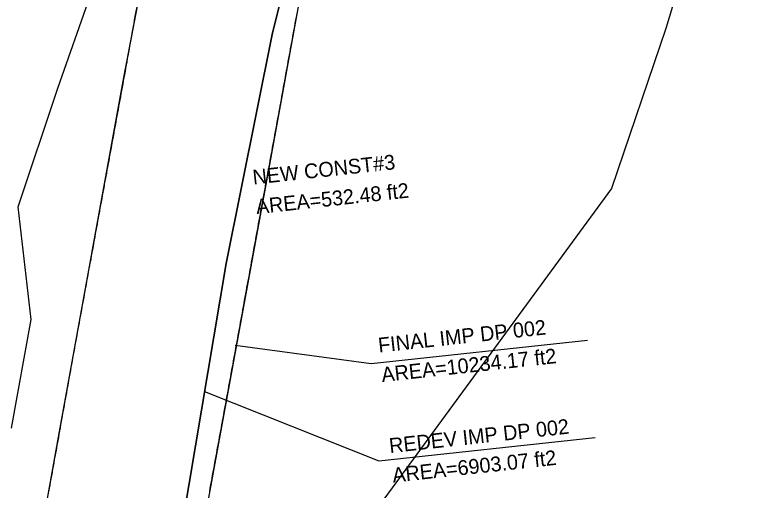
# Model space of a CAD drawing. Extents: x 1509538 to 1510847, y 401283 to 402022.
# Drawn here: x 1509743.9 to 1509883.9, y 401419.8 to 401509.5 of the extents above; entities that cross this region are included whole.
import ezdxf

# ---------------------------------------------------------------- set-up
doc = ezdxf.new("R2010")
doc.units = 0
for name, color, linetype in [('LAWE_P_T', 7, 'Continuous'), ('LDEFAULT_P', 7, 'Continuous'), ('Level 10', 7, 'Continuous'), ('Level 2', 7, 'Continuous'), ('Level 24', 7, 'Continuous'), ('Level 3', 7, 'Continuous'), ('Level 7', 7, 'Continuous')]:
    doc.layers.add(name, color=color, linetype=linetype)

msp = doc.modelspace()

# ---------------------------------------------------------------- linework, layer by layer
at = {"layer": 'LDEFAULT_P'}
for points in [[(1509785.49, 401447.11), (1509811.2, 401443.65), (1509852.03, 401448.1)], [(1509779.72, 401438.42), (1509812.63, 401425.29), (1509853.46, 401429.74)]]:
    msp.add_lwpolyline(points, dxfattribs=at)
at = {"layer": 'Level 10'}
for p, q in [((1509783.79, 401462.54), (1509792.46, 401505.8)), ((1509765.37, 401502.44), (1509765.29, 401502.03)), ((1509762.29, 401485.62), (1509762.23, 401485.31)), ((1509761.74, 401482.62), (1509761.69, 401482.35)), ((1509759.89, 401472.52), (1509759.76, 401471.8)), ((1509759.98, 401473.01), (1509759.89, 401472.52)), ((1509759.76, 401471.8), (1509759.72, 401471.53)), ((1509758.11, 401462.79), (1509758.09, 401462.68)), ((1509757.24, 401457.99), (1509757.2, 401457.76)), ((1509755.48, 401448.38), (1509755.4, 401447.93)), ((1509752.77, 401433.35), (1509752.74, 401433.16)), ((1509751.91, 401428.54), (1509751.85, 401428.24)), ((1509751.04, 401423.73), (1509750.97, 401423.32))]:
    msp.add_line(p, q, dxfattribs=at)
for points in [[(1509792.46, 401505.8), (1509800.22, 401536.88), (1509802.1, 401539.78)], [(1509767.14, 401511.86), (1509766.94, 401510.85), (1509766.81, 401510.25), (1509766.66, 401509.48)], [(1509766.66, 401509.48), (1509766.47, 401508.45), (1509766.36, 401507.85), (1509766.25, 401507.25), (1509766.19, 401506.95), (1509766.03, 401506.04), (1509765.92, 401505.44), (1509765.81, 401504.84), (1509765.7, 401504.24), (1509765.59, 401503.64), (1509765.48, 401503.04), (1509765.37, 401502.44)], [(1509765.29, 401502.03), (1509765.15, 401501.24), (1509765.04, 401500.64), (1509764.93, 401500.04), (1509764.82, 401499.44), (1509764.71, 401498.84), (1509764.6, 401498.24), (1509764.49, 401497.63), (1509764.39, 401497.11), (1509764.27, 401496.43), (1509764.16, 401495.83), (1509764.05, 401495.23), (1509763.94, 401494.63), (1509763.83, 401494.03), (1509763.72, 401493.43), (1509763.61, 401492.83), (1509763.5, 401492.23), (1509763.39, 401491.63), (1509763.28, 401491.03), (1509763.17, 401490.43), (1509763.06, 401489.83), (1509762.95, 401489.22), (1509762.84, 401488.62), (1509762.73, 401488.02), (1509762.62, 401487.42), (1509762.59, 401487.27), (1509762.4, 401486.22), (1509762.29, 401485.62)], [(1509762.23, 401485.31), (1509762.07, 401484.42), (1509761.96, 401483.82), (1509761.85, 401483.22), (1509761.74, 401482.62)], [(1509761.69, 401482.35), (1509761.52, 401481.42), (1509761.41, 401480.81), (1509761.3, 401480.21), (1509761.19, 401479.61), (1509761.08, 401479.01), (1509760.97, 401478.41), (1509760.86, 401477.81), (1509760.79, 401477.44), (1509760.64, 401476.61), (1509760.53, 401476.01), (1509760.42, 401475.41), (1509760.31, 401474.81), (1509760.2, 401474.21), (1509760.09, 401473.61), (1509759.98, 401473.01)], [(1509759.72, 401471.53), (1509759.54, 401470.6), (1509759.43, 401470), (1509759.32, 401469.4), (1509759.22, 401468.8), (1509759.1, 401468.2), (1509759, 401467.6), (1509758.88, 401467), (1509758.77, 401466.4), (1509758.67, 401465.8), (1509758.55, 401465.2), (1509758.44, 401464.6), (1509758.33, 401463.99), (1509758.23, 401463.39), (1509758.11, 401462.79)], [(1509758.09, 401462.68), (1509757.9, 401461.59), (1509757.78, 401460.99), (1509757.67, 401460.39), (1509757.57, 401459.79), (1509757.46, 401459.19), (1509757.35, 401458.59), (1509757.24, 401457.99)], [(1509772.64, 401396.18), (1509772.74, 401396.79), (1509775.66, 401414.3), (1509783.79, 401462.54)], [(1509757.2, 401457.76), (1509757.02, 401456.79), (1509756.91, 401456.19), (1509756.8, 401455.58), (1509756.69, 401454.98), (1509756.58, 401454.38), (1509756.47, 401453.78), (1509756.36, 401453.18), (1509756.3, 401452.84), (1509756.14, 401451.98), (1509756.03, 401451.38), (1509755.92, 401450.78), (1509755.81, 401450.18), (1509755.7, 401449.58), (1509755.59, 401448.98), (1509755.48, 401448.38)], [(1509755.4, 401447.93), (1509755.26, 401447.17), (1509755.16, 401446.57), (1509755.05, 401445.97), (1509754.94, 401445.37), (1509754.83, 401444.77), (1509754.72, 401444.17), (1509754.61, 401443.57), (1509754.51, 401443), (1509754.4, 401442.37), (1509754.29, 401441.76), (1509754.18, 401441.16), (1509754.07, 401440.56), (1509753.96, 401439.96), (1509753.86, 401439.36), (1509753.75, 401438.76), (1509753.64, 401438.16), (1509753.53, 401437.56), (1509753.42, 401436.96), (1509753.32, 401436.36), (1509753.21, 401435.75), (1509753.1, 401435.15), (1509752.99, 401434.55), (1509752.88, 401433.95), (1509752.77, 401433.35)], [(1509752.74, 401433.16), (1509752.56, 401432.15), (1509752.45, 401431.55), (1509752.34, 401430.95), (1509752.23, 401430.35), (1509752.13, 401429.74), (1509752.02, 401429.14), (1509751.91, 401428.54)], [(1509751.85, 401428.24), (1509751.69, 401427.34), (1509751.58, 401426.74), (1509751.48, 401426.14), (1509751.37, 401425.54), (1509751.26, 401424.94), (1509751.15, 401424.33), (1509751.04, 401423.73)], [(1509750.97, 401423.32), (1509750.83, 401422.53), (1509750.72, 401421.93), (1509750.61, 401421.33), (1509750.5, 401420.73), (1509750.39, 401420.13), (1509750.29, 401419.53)]]:
    msp.add_lwpolyline(points, dxfattribs=at)
at = {"layer": 'Level 2'}
for p, q in [((1509783.79, 401462.54), (1509792.46, 401505.8)), ((1509759.89, 401472.52), (1509759.76, 401471.8))]:
    msp.add_line(p, q, dxfattribs=at)
for points in [[(1509690.27, 401895.46), (1509701.64, 401882.87), (1509726.68, 401848.01), (1509747.74, 401803.4), (1509763.81, 401758.01), (1509775.46, 401713.07), (1509786.05, 401661.7), (1509787.8, 401644.85), (1509788.16, 401621.99), (1509786.62, 401596.26), (1509780.1, 401566.45), (1509768.35, 401517.81), (1509766.66, 401509.48)], [(1509772.31, 401394.18), (1509775.66, 401414.3), (1509783.79, 401462.54), (1509792.46, 401505.8), (1509800.22, 401536.88), (1509802.51, 401540.8)], [(1509792.46, 401505.8), (1509800.22, 401536.88), (1509802.1, 401539.78)], [(1509767.14, 401511.86), (1509766.94, 401510.85), (1509766.81, 401510.25), (1509766.66, 401509.48)], [(1509766.66, 401509.48), (1509766.58, 401509.05), (1509766.47, 401508.45), (1509766.36, 401507.85), (1509766.25, 401507.25), (1509766.19, 401506.95), (1509766.14, 401506.65), (1509766.03, 401506.04), (1509765.92, 401505.44), (1509765.81, 401504.84), (1509765.7, 401504.24), (1509765.59, 401503.64), (1509765.48, 401503.04), (1509765.37, 401502.44), (1509765.29, 401502.03), (1509765.26, 401501.84), (1509765.15, 401501.24), (1509765.04, 401500.64), (1509764.93, 401500.04), (1509764.82, 401499.44), (1509764.71, 401498.84), (1509764.6, 401498.24), (1509764.49, 401497.63), (1509764.39, 401497.11), (1509764.38, 401497.03), (1509764.27, 401496.43), (1509764.16, 401495.83), (1509764.05, 401495.23), (1509763.94, 401494.63), (1509763.83, 401494.03), (1509763.72, 401493.43), (1509763.61, 401492.83), (1509763.5, 401492.23), (1509763.49, 401492.19), (1509763.39, 401491.63), (1509763.28, 401491.03), (1509763.17, 401490.43), (1509763.06, 401489.83), (1509762.95, 401489.22), (1509762.84, 401488.62), (1509762.73, 401488.02), (1509762.62, 401487.42), (1509762.59, 401487.27), (1509762.51, 401486.82), (1509762.4, 401486.22), (1509762.29, 401485.62), (1509762.23, 401485.31), (1509762.18, 401485.02), (1509762.07, 401484.42), (1509761.96, 401483.82), (1509761.85, 401483.22), (1509761.74, 401482.62), (1509761.69, 401482.35), (1509761.63, 401482.02), (1509761.52, 401481.42), (1509761.41, 401480.81), (1509761.3, 401480.21), (1509761.19, 401479.61), (1509761.08, 401479.01), (1509760.97, 401478.41), (1509760.86, 401477.81), (1509760.79, 401477.44), (1509760.75, 401477.21), (1509760.64, 401476.61), (1509760.53, 401476.01), (1509760.42, 401475.41), (1509760.31, 401474.81), (1509760.2, 401474.21), (1509760.09, 401473.61), (1509759.98, 401473.01), (1509759.89, 401472.52), (1509759.87, 401472.4), (1509759.76, 401471.8), (1509759.72, 401471.53), (1509759.65, 401471.2), (1509759.54, 401470.6), (1509759.43, 401470), (1509759.32, 401469.4), (1509759.22, 401468.8), (1509759.1, 401468.2), (1509759, 401467.6), (1509758.88, 401467), (1509758.77, 401466.4), (1509758.67, 401465.8), (1509758.55, 401465.2), (1509758.44, 401464.6), (1509758.33, 401463.99), (1509758.23, 401463.39), (1509758.11, 401462.79), (1509758.09, 401462.68), (1509758, 401462.19), (1509757.9, 401461.59), (1509757.78, 401460.99), (1509757.67, 401460.39), (1509757.57, 401459.79), (1509757.46, 401459.19), (1509757.35, 401458.59), (1509757.24, 401457.99), (1509757.2, 401457.76), (1509757.13, 401457.39), (1509757.02, 401456.79), (1509756.91, 401456.19), (1509756.8, 401455.58), (1509756.69, 401454.98), (1509756.58, 401454.38), (1509756.47, 401453.78), (1509756.36, 401453.18), (1509756.3, 401452.84), (1509756.25, 401452.58), (1509756.14, 401451.98), (1509756.03, 401451.38), (1509755.92, 401450.78), (1509755.81, 401450.18), (1509755.7, 401449.58), (1509755.59, 401448.98), (1509755.48, 401448.38), (1509755.4, 401447.93), (1509755.37, 401447.78), (1509755.26, 401447.17), (1509755.16, 401446.57), (1509755.05, 401445.97), (1509754.94, 401445.37), (1509754.83, 401444.77), (1509754.72, 401444.17), (1509754.61, 401443.57), (1509754.51, 401443), (1509754.51, 401442.97), (1509754.4, 401442.37), (1509754.29, 401441.76), (1509754.18, 401441.16), (1509754.07, 401440.56), (1509753.96, 401439.96), (1509753.86, 401439.36), (1509753.75, 401438.76), (1509753.64, 401438.16), (1509753.63, 401438.08), (1509753.53, 401437.56), (1509753.42, 401436.96), (1509753.32, 401436.36), (1509753.21, 401435.75), (1509753.1, 401435.15), (1509752.99, 401434.55), (1509752.88, 401433.95), (1509752.77, 401433.35), (1509752.74, 401433.16), (1509752.67, 401432.75), (1509752.56, 401432.15), (1509752.45, 401431.55), (1509752.34, 401430.95), (1509752.23, 401430.35), (1509752.13, 401429.74), (1509752.02, 401429.14), (1509751.91, 401428.54), (1509751.85, 401428.24), (1509751.8, 401427.94), (1509751.69, 401427.34), (1509751.58, 401426.74), (1509751.48, 401426.14), (1509751.37, 401425.54), (1509751.26, 401424.94), (1509751.15, 401424.33), (1509751.04, 401423.73), (1509750.97, 401423.32), (1509750.93, 401423.13), (1509750.83, 401422.53), (1509750.72, 401421.93), (1509750.61, 401421.33), (1509750.5, 401420.73), (1509750.39, 401420.13), (1509750.29, 401419.53)], [(1509766.66, 401509.48), (1509766.47, 401508.45), (1509766.36, 401507.85), (1509766.25, 401507.25), (1509766.19, 401506.95), (1509766.03, 401506.04), (1509765.92, 401505.44), (1509765.81, 401504.84), (1509765.7, 401504.24), (1509765.59, 401503.64), (1509765.48, 401503.04), (1509765.37, 401502.44)], [(1509765.29, 401502.03), (1509765.15, 401501.24), (1509765.04, 401500.64), (1509764.93, 401500.04), (1509764.82, 401499.44), (1509764.71, 401498.84), (1509764.6, 401498.24), (1509764.49, 401497.63), (1509764.39, 401497.11), (1509764.27, 401496.43), (1509764.16, 401495.83), (1509764.05, 401495.23), (1509763.94, 401494.63), (1509763.83, 401494.03), (1509763.72, 401493.43), (1509763.61, 401492.83), (1509763.5, 401492.23), (1509763.39, 401491.63), (1509763.28, 401491.03), (1509763.17, 401490.43), (1509763.06, 401489.83), (1509762.95, 401489.22), (1509762.84, 401488.62), (1509762.73, 401488.02), (1509762.62, 401487.42), (1509762.59, 401487.27), (1509762.4, 401486.22), (1509762.29, 401485.62)], [(1509765.37, 401502.44), (1509765.29, 401502.03)], [(1509762.23, 401485.31), (1509762.07, 401484.42), (1509761.96, 401483.82), (1509761.85, 401483.22), (1509761.74, 401482.62)], [(1509762.29, 401485.62), (1509762.23, 401485.31)], [(1509761.69, 401482.35), (1509761.52, 401481.42), (1509761.41, 401480.81), (1509761.3, 401480.21), (1509761.19, 401479.61), (1509761.08, 401479.01), (1509760.97, 401478.41), (1509760.86, 401477.81), (1509760.79, 401477.44), (1509760.64, 401476.61), (1509760.53, 401476.01), (1509760.42, 401475.41), (1509760.31, 401474.81), (1509760.2, 401474.21), (1509760.09, 401473.61), (1509759.98, 401473.01)], [(1509761.74, 401482.62), (1509761.69, 401482.35)], [(1509759.98, 401473.01), (1509759.89, 401472.52)], [(1509759.72, 401471.53), (1509759.54, 401470.6), (1509759.43, 401470), (1509759.32, 401469.4), (1509759.22, 401468.8), (1509759.1, 401468.2), (1509759, 401467.6), (1509758.88, 401467), (1509758.77, 401466.4), (1509758.67, 401465.8), (1509758.55, 401465.2), (1509758.44, 401464.6), (1509758.33, 401463.99), (1509758.23, 401463.39), (1509758.11, 401462.79)], [(1509759.76, 401471.8), (1509759.72, 401471.53)], [(1509758.09, 401462.68), (1509757.9, 401461.59), (1509757.78, 401460.99), (1509757.67, 401460.39), (1509757.57, 401459.79), (1509757.46, 401459.19), (1509757.35, 401458.59), (1509757.24, 401457.99)], [(1509758.11, 401462.79), (1509758.09, 401462.68)], [(1509772.64, 401396.18), (1509772.74, 401396.79), (1509775.66, 401414.3), (1509783.79, 401462.54)], [(1509757.2, 401457.76), (1509757.02, 401456.79), (1509756.91, 401456.19), (1509756.8, 401455.58), (1509756.69, 401454.98), (1509756.58, 401454.38), (1509756.47, 401453.78), (1509756.36, 401453.18), (1509756.3, 401452.84), (1509756.14, 401451.98), (1509756.03, 401451.38), (1509755.92, 401450.78), (1509755.81, 401450.18), (1509755.7, 401449.58), (1509755.59, 401448.98), (1509755.48, 401448.38)], [(1509757.24, 401457.99), (1509757.2, 401457.76)], [(1509755.48, 401448.38), (1509755.4, 401447.93)], [(1509755.4, 401447.93), (1509755.26, 401447.17), (1509755.16, 401446.57), (1509755.05, 401445.97), (1509754.94, 401445.37), (1509754.83, 401444.77), (1509754.72, 401444.17), (1509754.61, 401443.57), (1509754.51, 401443), (1509754.4, 401442.37), (1509754.29, 401441.76), (1509754.18, 401441.16), (1509754.07, 401440.56), (1509753.96, 401439.96), (1509753.86, 401439.36), (1509753.75, 401438.76), (1509753.64, 401438.16), (1509753.53, 401437.56), (1509753.42, 401436.96), (1509753.32, 401436.36), (1509753.21, 401435.75), (1509753.1, 401435.15), (1509752.99, 401434.55), (1509752.88, 401433.95), (1509752.77, 401433.35)], [(1509752.74, 401433.16), (1509752.56, 401432.15), (1509752.45, 401431.55), (1509752.34, 401430.95), (1509752.23, 401430.35), (1509752.13, 401429.74), (1509752.02, 401429.14), (1509751.91, 401428.54)], [(1509752.77, 401433.35), (1509752.74, 401433.16)], [(1509751.85, 401428.24), (1509751.69, 401427.34), (1509751.58, 401426.74), (1509751.48, 401426.14), (1509751.37, 401425.54), (1509751.26, 401424.94), (1509751.15, 401424.33), (1509751.04, 401423.73)], [(1509751.91, 401428.54), (1509751.85, 401428.24)], [(1509750.97, 401423.32), (1509750.83, 401422.53), (1509750.72, 401421.93), (1509750.61, 401421.33), (1509750.5, 401420.73), (1509750.39, 401420.13), (1509750.29, 401419.53)], [(1509751.04, 401423.73), (1509750.97, 401423.32)]]:
    msp.add_lwpolyline(points, dxfattribs=at)
at = {"layer": 'Level 24'}
for points in [[(1509829.75, 401765.91), (1509866.1, 401667.73), (1509876.61, 401577.47), (1509875.57, 401568.19), (1509883.85, 401563.18), (1509866.77, 401506.88), (1509856.53, 401476.73), (1509809.07, 401412), (1509809.1, 401403.54), (1509796.56, 401386.39), (1509783.48, 401379.52), (1509778.17, 401371.6), (1509774.1, 401368.36), (1509767.58, 401349.35), (1509764.23, 401344.65), (1509737.94, 401349.46)], [(1509743.29, 401431.45), (1509746.99, 401452), (1509744.57, 401473.27), (1509752.01, 401495.65), (1509758.16, 401513.05), (1509760.49, 401532.85), (1509750.72, 401537.98), (1509756.25, 401578.96), (1509758.43, 401599.41), (1509758.86, 401632.41), (1509758.36, 401648.49), (1509754.99, 401675.99), (1509750.34, 401698.83)]]:
    msp.add_lwpolyline(points, dxfattribs=at)
at = {"layer": 'Level 3'}
for points in [[(1509802.51, 401540.8), (1509800.22, 401536.88), (1509792.46, 401505.8)], [(1509780.7, 401419.55), (1509780.81, 401420.15), (1509780.92, 401420.75), (1509781.03, 401421.35), (1509781.14, 401421.95), (1509781.25, 401422.55), (1509781.3, 401422.85), (1509781.36, 401423.15), (1509781.47, 401423.75), (1509781.58, 401424.35), (1509781.69, 401424.96), (1509781.8, 401425.56), (1509781.91, 401426.16), (1509782.02, 401426.76), (1509782.13, 401427.36), (1509782.2, 401427.77), (1509782.24, 401427.96), (1509782.35, 401428.56), (1509782.46, 401429.16), (1509782.57, 401429.76), (1509782.68, 401430.36), (1509782.79, 401430.96), (1509782.9, 401431.56), (1509783.01, 401432.16), (1509783.1, 401432.69), (1509783.12, 401432.77), (1509783.23, 401433.36), (1509783.34, 401433.97), (1509783.45, 401434.57), (1509783.56, 401435.17), (1509783.67, 401435.77), (1509783.78, 401436.37), (1509783.89, 401436.97), (1509784, 401437.57), (1509784, 401437.61), (1509784.11, 401438.17), (1509784.22, 401438.77), (1509784.33, 401439.37), (1509784.44, 401439.97), (1509784.55, 401440.57), (1509784.66, 401441.17), (1509784.77, 401441.78), (1509784.88, 401442.38), (1509784.9, 401442.53), (1509784.99, 401442.98), (1509785.1, 401443.58), (1509785.21, 401444.18), (1509785.32, 401444.78), (1509785.43, 401445.38), (1509785.54, 401445.98), (1509785.65, 401446.58), (1509785.76, 401447.18), (1509785.8, 401447.44), (1509785.87, 401447.78), (1509785.98, 401448.38), (1509786.09, 401448.98), (1509786.2, 401449.58), (1509786.31, 401450.18), (1509786.42, 401450.79), (1509786.53, 401451.39), (1509786.64, 401451.99), (1509786.7, 401452.36), (1509786.75, 401452.59), (1509786.86, 401453.19), (1509786.97, 401453.79), (1509787.08, 401454.39), (1509787.19, 401454.99), (1509787.29, 401455.59), (1509787.41, 401456.19), (1509787.51, 401456.79), (1509787.6, 401457.28), (1509787.62, 401457.39), (1509787.73, 401457.99), (1509787.84, 401458.59), (1509787.96, 401459.2), (1509788.06, 401459.8), (1509788.18, 401460.4), (1509788.28, 401461), (1509788.4, 401461.6), (1509788.5, 401462.2), (1509788.61, 401462.8), (1509788.72, 401463.4), (1509788.83, 401464), (1509788.94, 401464.6), (1509789.05, 401465.2), (1509789.16, 401465.8), (1509789.23, 401466.13), (1509789.27, 401466.4), (1509789.38, 401467.01), (1509789.41, 401467.12), (1509789.49, 401467.61), (1509789.6, 401468.21), (1509789.71, 401468.81), (1509789.82, 401469.41), (1509789.93, 401470.01), (1509790.04, 401470.61), (1509790.15, 401471.21), (1509790.26, 401471.81), (1509790.3, 401472.04), (1509790.37, 401472.41), (1509790.48, 401473.01), (1509790.59, 401473.61), (1509790.7, 401474.21), (1509790.81, 401474.81), (1509790.92, 401475.41), (1509791.03, 401476.02), (1509791.14, 401476.62), (1509791.21, 401476.95), (1509791.25, 401477.22), (1509791.36, 401477.82), (1509791.47, 401478.42), (1509791.58, 401479.02), (1509791.69, 401479.62), (1509791.75, 401479.91), (1509791.8, 401480.22), (1509791.91, 401480.82), (1509792.02, 401481.42), (1509792.1, 401481.87), (1509792.13, 401482.02), (1509792.24, 401482.62), (1509792.35, 401483.22), (1509792.46, 401483.83), (1509792.57, 401484.43), (1509792.68, 401485.03), (1509792.79, 401485.63), (1509792.9, 401486.23), (1509793, 401486.79), (1509793.01, 401486.83), (1509793.12, 401487.43), (1509793.23, 401488.03), (1509793.34, 401488.63), (1509793.45, 401489.23), (1509793.56, 401489.83), (1509793.67, 401490.43), (1509793.78, 401491.03), (1509793.89, 401491.63), (1509793.91, 401491.71), (1509794, 401492.23), (1509794.11, 401492.84), (1509794.22, 401493.44), (1509794.33, 401494.04), (1509794.44, 401494.64), (1509794.55, 401495.24), (1509794.66, 401495.84), (1509794.77, 401496.44), (1509794.8, 401496.63), (1509794.88, 401497.04), (1509794.99, 401497.64), (1509795.1, 401498.24), (1509795.21, 401498.84), (1509795.32, 401499.44), (1509795.43, 401500.04), (1509795.54, 401500.65), (1509795.65, 401501.25), (1509795.7, 401501.55), (1509795.76, 401501.85), (1509795.87, 401502.45), (1509795.98, 401503.05), (1509796.09, 401503.65), (1509796.2, 401504.25), (1509796.31, 401504.85), (1509796.42, 401505.45), (1509796.53, 401506.05), (1509796.6, 401506.46), (1509796.64, 401506.65), (1509796.75, 401507.25), (1509796.86, 401507.85), (1509796.97, 401508.45), (1509797.08, 401509.05), (1509797.19, 401509.66)], [(1509792.46, 401505.8), (1509783.79, 401462.54), (1509775.66, 401414.3)]]:
    msp.add_lwpolyline(points, dxfattribs=at)
at = {"layer": 'Level 7'}
for p, q in [((1509800.64, 401528.8), (1509792.24, 401482.62)), ((1509800.64, 401528.8), (1509792.24, 401482.62)), ((1509764.49, 401497.63), (1509767.66, 401514.26)), ((1509764.49, 401497.63), (1509767.66, 401514.26)), ((1509752.45, 401431.55), (1509764.49, 401497.63)), ((1509752.45, 401431.55), (1509764.49, 401497.63)), ((1509792.24, 401482.62), (1509780.48, 401418.35)), ((1509792.24, 401482.62), (1509780.48, 401418.35)), ((1509746.6, 401398.71), (1509752.45, 401431.55)), ((1509746.6, 401398.71), (1509752.45, 401431.55))]:
    msp.add_line(p, q, dxfattribs=at)

# ---------------------------------------------------------------- texts
at = {"layer": 'LAWE_P_T'}
for s, p in [('NEW CONST#3', (1509788.95, 401477.43)), ('AREA=532.48 ft2', (1509789.56, 401471.86))]:
    msp.add_text(s, height=2.8, rotation=6.2219, dxfattribs=at).set_placement(p)
at = {"layer": 'LDEFAULT_P'}
for s, p in [('FINAL IMP DP 002', (1509812.65, 401445.72)), ('AREA=10234.17 ft2', (1509813.26, 401440.16)), ('REDEV IMP DP 002', (1509814.72, 401426.76)), ('AREA=6903.07 ft2', (1509815.32, 401421.19))]:
    msp.add_text(s, height=2.8, rotation=6.2219, dxfattribs=at).set_placement(p)

doc.saveas('drawing.dxf')
